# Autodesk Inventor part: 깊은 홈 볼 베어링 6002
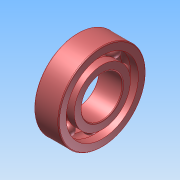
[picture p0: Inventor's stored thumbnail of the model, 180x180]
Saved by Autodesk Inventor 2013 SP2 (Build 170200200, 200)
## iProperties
Created: 2025-10
Part Number: 깊은 홈 볼 베어링 6002
Material: Generic
Document SubType Name: Modeling
Designer: a
Density: 1 g/cm^3
Author: a
변환 표준: STEP AP214IS
전처리기: Build: 200, Release: 2013 SP2 Update 6 - Date: Thu 07/17/2014
전송 단위: 밀리미터
불확실성: 0.01
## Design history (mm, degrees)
node "깊은 홈 볼 베어링 60021"
body "Solid1"
node "Solid1_1"
node "Solid1_2"
node "Solid1_3"
node "Solid1_4"
node "Solid1_5"
node "Solid1_6"
node "Solid1_7"
node "Solid1_8"
node "Solid1_9"
node "기준1"
node "기준2"
node "기준3"
node "기준4"
node "기준5"
node "기준6"
node "기준7"
node "기준8"
node "기준9"
node "기준10"
